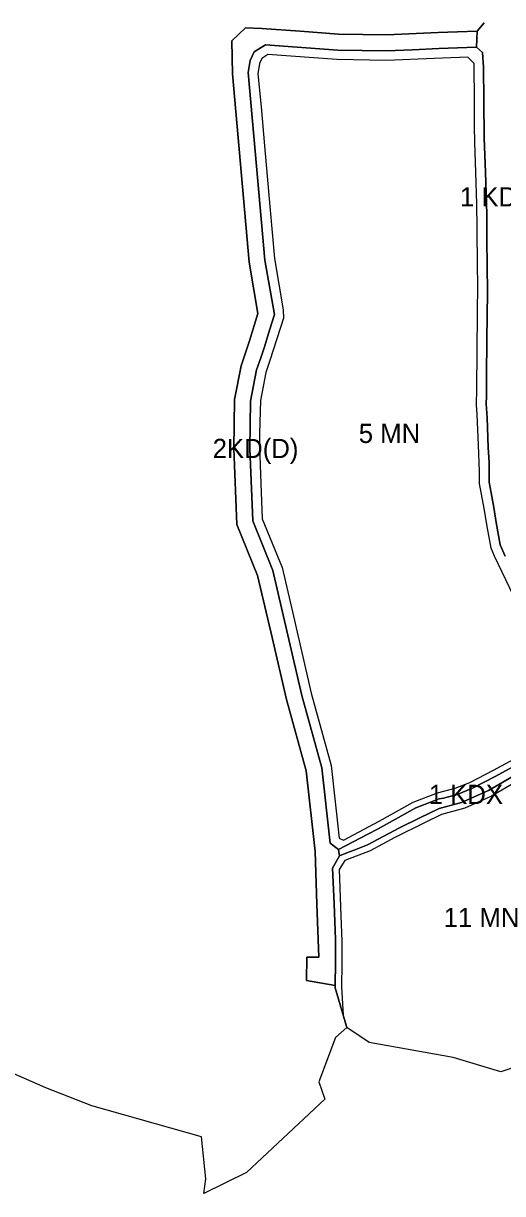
# Model space of a CAD drawing. Extents: x 7437690 to 7439067, y 5547517 to 5548678.
# Drawn here: x 7438219 to 7438518, y 5547517 to 5548247 of the extents above; entities that cross this region are included whole.
import ezdxf

# ---------------------------------------------------------------- set-up
doc = ezdxf.new("R2010")
doc.units = 0
for name, color, linetype in [('linie_rozgraniczajace', 7, 'Continuous'), ('linie_zabudowy_nieprzekraczalne', 7, 'Continuous'), ('oznaczenia_przeznaczen', 7, 'Continuous')]:
    doc.layers.add(name, color=color, linetype=linetype)

msp = doc.modelspace()

# ---------------------------------------------------------------- linework, layer by layer
at = {"layer": 'linie_rozgraniczajace'}
for points in [[(7438506.2, 5548247.42), (7438502, 5548242.29), (7438489.75, 5548241.8), (7438477.49, 5548241.31)], [(7438509.39, 5547960.7), (7438509.35, 5547966.82), (7438509.31, 5547972.94), (7438508.87, 5547982.43), (7438508.17, 5548000.77), (7438507.54, 5548009.53), (7438507.64, 5548014.35), (7438507.74, 5548019.17), (7438507.76, 5548026.64), (7438507.92, 5548049.82), (7438508.42, 5548079.36), (7438508.06, 5548095.8), (7438508.02, 5548111.91), (7438507.97, 5548128.02), (7438507.14, 5548154.3), (7438506.37, 5548175.32), (7438506.18, 5548199.03), (7438505.91, 5548219.82), (7438505.34, 5548228.87), (7438501.51, 5548232.24), (7438502, 5548242.29), (7438506.2, 5548247.42)], [(7438477.49, 5548241.31), (7438445.6, 5548239.92), (7438430.51, 5548240.15), (7438415.41, 5548240.39), (7438391.53, 5548242.13), (7438367.64, 5548243.88), (7438357.43, 5548244.36), (7438348.93, 5548236.09), (7438349.26, 5548215.56), (7438359.64, 5548098.08), (7438365.15, 5548065.92), (7438359.97, 5548048.82), (7438354.69, 5548033.34), (7438350.57, 5548012.32), (7438350.35, 5547996.97), (7438350.12, 5547981.62), (7438351.98, 5547934.33), (7438364.99, 5547902.55), (7438373.98, 5547863.85), (7438382.96, 5547825.16), (7438395.25, 5547780.48), (7438400.81, 5547730.2), (7438401.96, 5547697.21), (7438403.11, 5547664.21), (7438395.58, 5547664.29), (7438395.43, 5547649.64), (7438413.39, 5547646.48), (7438413.38, 5547645.04), (7438420.73, 5547620.42), (7438413.52, 5547614.01), (7438403.1, 5547586.34), (7438406.96, 5547575.66), (7438358.08, 5547529.77), (7438331.49, 5547516.66), (7438332.63, 5547525.92), (7438330.08, 5547552.02), (7438261.53, 5547571.42), (7438232.91, 5547582.65), (7438184.96, 5547603.78)], [(7438528.84, 5547785.53), (7438513.14, 5547777.05), (7438499.08, 5547769.63), (7438489.39, 5547765.84), (7438480.88, 5547763.49), (7438478.3, 5547762.99), (7438463.72, 5547757.39), (7438440.23, 5547744.23), (7438433.79, 5547740.91), (7438415.52, 5547731.49), (7438410.3, 5547735.36), (7438405.1, 5547782.37), (7438392.65, 5547827.61), (7438374.55, 5547905.59), (7438361.9, 5547936.49), (7438360.12, 5547981.74), (7438360.56, 5548011.27), (7438364.38, 5548030.75), (7438366.93, 5548038.25), (7438369.49, 5548045.76), (7438372.45, 5548055.52), (7438375.41, 5548065.27), (7438369.57, 5548099.37), (7438364.37, 5548157.91), (7438359.18, 5548216.44), (7438360.31, 5548223.81), (7438362.83, 5548229.34), (7438369.85, 5548233.69), (7438414.97, 5548230.4), (7438445.44, 5548229.9), (7438461.67, 5548230.61), (7438477.91, 5548231.32), (7438489.71, 5548231.78), (7438501.51, 5548232.24), (7438505.34, 5548228.87), (7438505.91, 5548219.82), (7438506.18, 5548199.03), (7438506.37, 5548175.32), (7438507.14, 5548154.3), (7438507.97, 5548128.02), (7438508.02, 5548111.91), (7438508.06, 5548095.8), (7438508.42, 5548079.36), (7438507.92, 5548049.82), (7438507.76, 5548026.64), (7438507.74, 5548019.17), (7438507.64, 5548014.35), (7438507.54, 5548009.53), (7438508.17, 5548000.77), (7438508.87, 5547982.43), (7438509.31, 5547972.94), (7438509.35, 5547966.82), (7438509.39, 5547960.7), (7438510.74, 5547953.99), (7438512.27, 5547944.86), (7438513.85, 5547935.53), (7438516.29, 5547921.54), (7438519.32, 5547914.44)], [(7438519.32, 5547914.44), (7438516.29, 5547921.54), (7438513.85, 5547935.53), (7438512.27, 5547944.86), (7438510.74, 5547953.99), (7438509.39, 5547960.7)], [(7438524.42, 5547777.28), (7438509.09, 5547768.33), (7438492.13, 5547760.77), (7438478.14, 5547756.98), (7438465.83, 5547750.92), (7438453.52, 5547744.87), (7438433.43, 5547734.25), (7438425.16, 5547731.01), (7438420.57, 5547729.25), (7438415.99, 5547727.48), (7438415.52, 5547731.49), (7438433.79, 5547740.91), (7438440.23, 5547744.23), (7438463.72, 5547757.39), (7438478.3, 5547762.99), (7438480.88, 5547763.49), (7438489.39, 5547765.84), (7438499.08, 5547769.63), (7438513.14, 5547777.05), (7438528.84, 5547785.53)], [(7438551.53, 5547604.42), (7438516.71, 5547592.74), (7438486.94, 5547601.51), (7438434.54, 5547610.89), (7438420.73, 5547620.42), (7438413.38, 5547645.04), (7438413.39, 5547646.48), (7438413.48, 5547660.88), (7438413.58, 5547675.28), (7438412.64, 5547697.55), (7438411.71, 5547719.81), (7438415.99, 5547727.48), (7438420.57, 5547729.25), (7438425.16, 5547731.01), (7438433.43, 5547734.25), (7438453.52, 5547744.87), (7438465.83, 5547750.92), (7438478.14, 5547756.98), (7438492.13, 5547760.77), (7438509.09, 5547768.33), (7438524.42, 5547777.28)]]:
    msp.add_lwpolyline(points, dxfattribs=at)
msp.add_lwpolyline([(7438351.98, 5547934.33), (7438350.12, 5547981.62), (7438350.35, 5547996.97), (7438350.57, 5548012.32), (7438354.69, 5548033.34), (7438359.97, 5548048.82), (7438365.15, 5548065.92), (7438359.64, 5548098.08), (7438349.26, 5548215.56), (7438348.93, 5548236.09), (7438357.43, 5548244.36), (7438367.64, 5548243.88), (7438391.53, 5548242.13), (7438415.41, 5548240.39), (7438430.51, 5548240.15), (7438445.6, 5548239.92), (7438477.49, 5548241.31), (7438489.75, 5548241.8), (7438502, 5548242.29), (7438501.51, 5548232.24), (7438489.71, 5548231.78), (7438477.91, 5548231.32), (7438461.67, 5548230.61), (7438445.44, 5548229.9), (7438414.97, 5548230.4), (7438369.85, 5548233.69), (7438362.83, 5548229.34), (7438360.31, 5548223.81), (7438359.18, 5548216.44), (7438364.37, 5548157.91), (7438369.57, 5548099.37), (7438375.41, 5548065.27), (7438372.45, 5548055.52), (7438369.49, 5548045.76), (7438366.93, 5548038.25), (7438364.38, 5548030.75), (7438360.56, 5548011.27), (7438360.12, 5547981.74), (7438361.9, 5547936.49), (7438374.55, 5547905.59), (7438392.65, 5547827.61), (7438405.1, 5547782.37), (7438410.3, 5547735.36), (7438415.52, 5547731.49), (7438415.99, 5547727.48), (7438411.71, 5547719.81), (7438412.64, 5547697.55), (7438413.58, 5547675.28), (7438413.48, 5547660.88), (7438413.39, 5547646.48), (7438395.43, 5547649.64), (7438395.58, 5547664.29), (7438403.11, 5547664.21), (7438401.96, 5547697.21), (7438400.81, 5547730.2), (7438395.25, 5547780.48), (7438382.96, 5547825.16), (7438373.98, 5547863.85), (7438364.99, 5547902.55)], close=True, dxfattribs=at)
at = {"layer": 'linie_zabudowy_nieprzekraczalne'}
for points in [[(7438499.98, 5548221.94), (7438496.11, 5548226.04), (7438475.13, 5548225.19), (7438445.34, 5548223.9), (7438414.35, 5548224.43), (7438371.35, 5548227.56), (7438367.53, 5548225.2), (7438366.12, 5548222.08), (7438365.11, 5548215.53), (7438367.11, 5548195.02), (7438369.27, 5548170.61), (7438372.63, 5548132.76), (7438375.49, 5548100.39), (7438380.97, 5548068.36), (7438381.08, 5548063.13), (7438372.69, 5548036.56), (7438370.19, 5548029.2), (7438366.8, 5548011.66), (7438366.22, 5547991.16), (7438366.14, 5547983.05), (7438366.99, 5547959.79), (7438367.85, 5547937.78), (7438380.29, 5547907.42), (7438386.71, 5547879.78), (7438398.47, 5547829.09), (7438410.93, 5547783.81), (7438415.92, 5547738.57), (7438418.65, 5547737.19), (7438440.81, 5547749.14), (7438462.01, 5547761.02), (7438477.19, 5547766.85), (7438488.13, 5547769.64), (7438497.41, 5547773.27), (7438512.16, 5547781.05), (7438527.11, 5547789.14)], [(7438524.88, 5547889.31), (7438512.75, 5547914.54), (7438510.57, 5547919.59), (7438508.39, 5547931.9), (7438506.29, 5547944.22), (7438503.41, 5547959.95), (7438503.35, 5547967.45), (7438502.79, 5547983.94), (7438502, 5548002.92), (7438501.56, 5548008.9), (7438501.74, 5548018.9), (7438502.19, 5548065.89), (7438502.36, 5548084.09), (7438502.06, 5548095.72), (7438501.99, 5548118.88), (7438501.77, 5548134.38), (7438501.15, 5548154.09), (7438500.48, 5548172.85), (7438500.31, 5548182.85), (7438500.21, 5548195.35), (7438500.26, 5548200.34), (7438500.05, 5548219.26), (7438500.02, 5548221), (7438499.98, 5548221.94)], [(7438600.67, 5547737.73), (7438589.4, 5547760.88), (7438580.28, 5547777.84), (7438571.69, 5547793.85), (7438568.67, 5547795.26), (7438559.75, 5547791.42), (7438545.1, 5547783.83), (7438536.98, 5547778.84), (7438526.18, 5547773.69), (7438510.91, 5547764.77), (7438494.19, 5547757.3), (7438479.75, 5547753.29), (7438468.97, 5547748.01), (7438450.63, 5547738.86), (7438435.19, 5547730.64), (7438419.34, 5547724.49), (7438415.85, 5547719.05), (7438416.96, 5547689.99), (7438417.57, 5547674.16), (7438417.48, 5547660.48), (7438417.38, 5547645.61), (7438418.44, 5547628.08)]]:
    msp.add_lwpolyline(points, dxfattribs=at)

# ---------------------------------------------------------------- texts
at = {"layer": 'oznaczenia_przeznaczen'}
for s, p in [('1 KD(L)', (7438491.18, 5548132.81)), ('5 MN', (7438428.07, 5547985.17)), ('2KD(D)', (7438336.95, 5547975.74)), ('1 KDX', (7438471.69, 5547759.82)), ('11 MN', (7438481.04, 5547683.02))]:
    msp.add_text(s, height=12, dxfattribs=at).set_placement(p)

doc.saveas('drawing.dxf')
